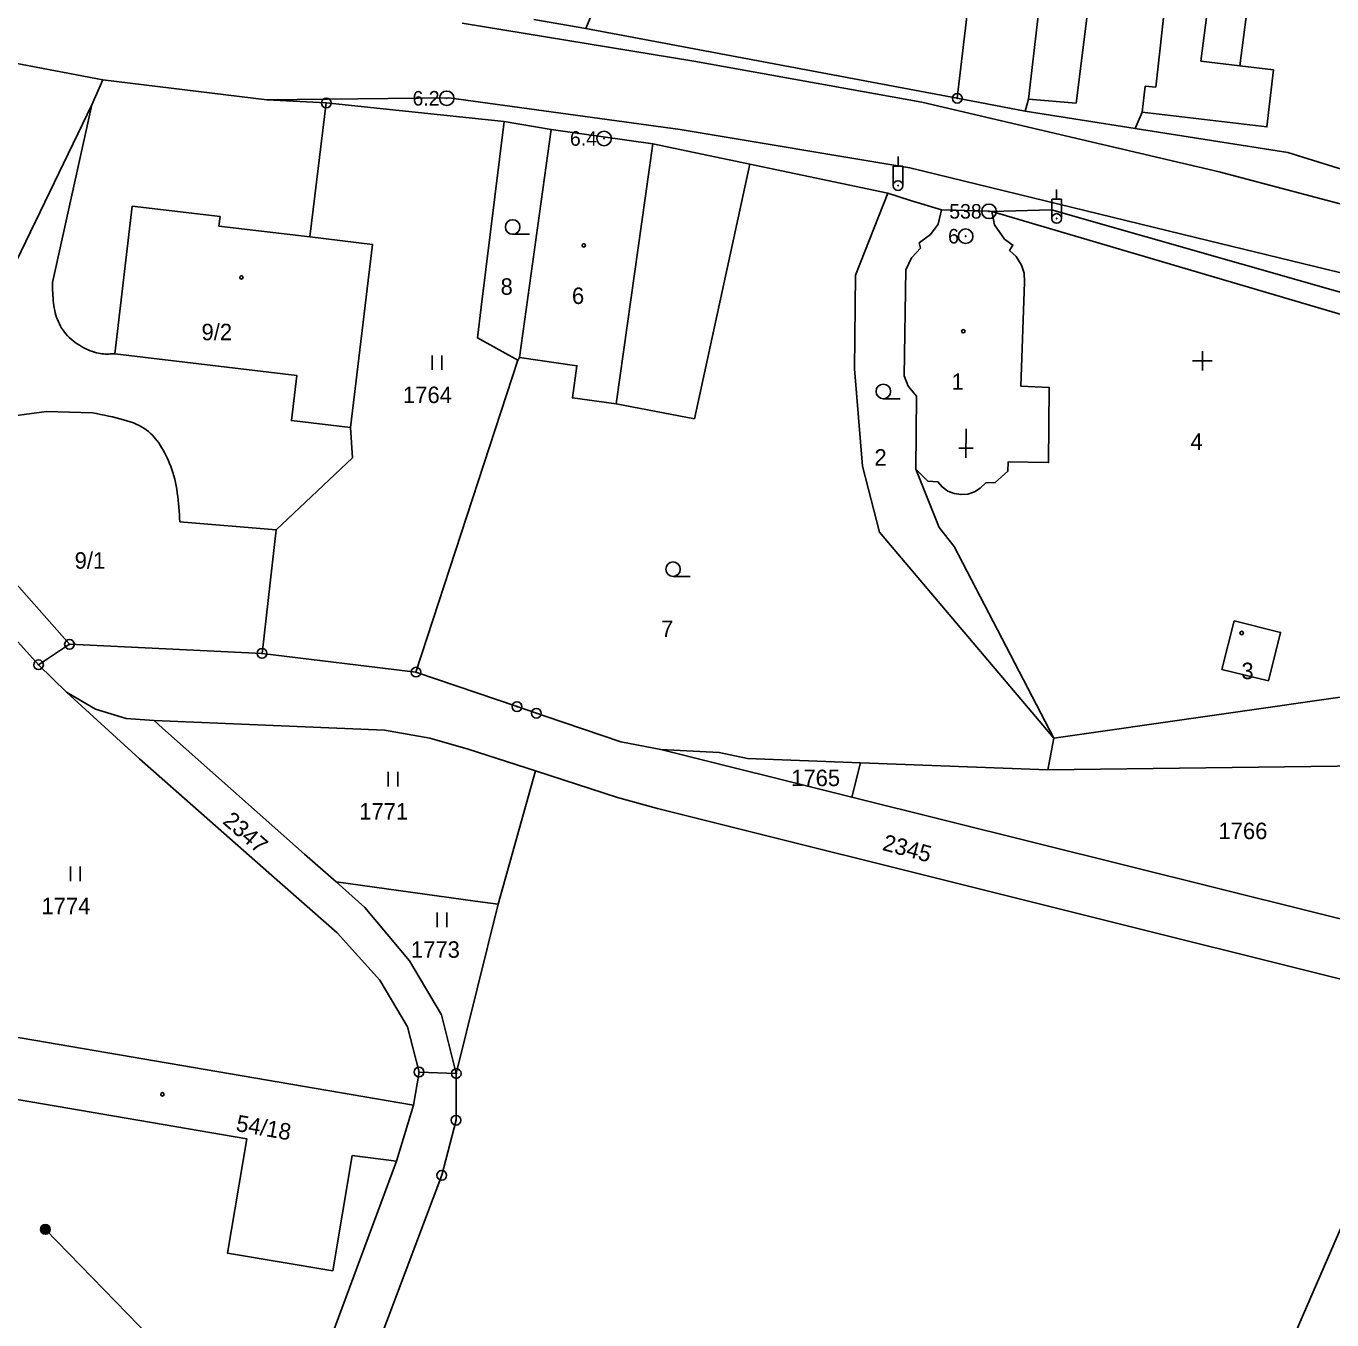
# Model space of a CAD drawing. Extents: x -504988 to -494607, y -1123820 to -1114018.
# Drawn here: x -501208.2 to -501073.4, y -1121149.7 to -1121016.1 of the extents above; entities that cross this region are included whole.
import ezdxf

# ---------------------------------------------------------------- set-up
doc = ezdxf.new("R2010")
doc.units = 0
for name, color, linetype in [('Hranice parcel', 7, 'Continuous'), ('Parcelní čísla', 7, 'Continuous'), ('Poz předměty', 7, 'Continuous'), ('Vnitřní kresba', 7, 'Continuous'), ('Značky bodu BP', 7, 'Continuous'), ('Značky budov', 7, 'Continuous'), ('Značky kultur', 7, 'Continuous')]:
    doc.layers.add(name, color=color, linetype=linetype)

msp = doc.modelspace()

# ---------------------------------------------------------------- linework, layer by layer
at = {"layer": 'Hranice parcel'}
for p, q in [((-501150.45, -1121016.36), (-501142.32, -1120996.7)), ((-501112.09, -1121023.57), (-501109.46, -1121001.03)), ((-501155.79, -1121015.45), (-501150.45, -1121016.36)), ((-501112.09, -1121023.57), (-501150.45, -1121016.36)), ((-501200.31, -1121021.65), (-501210.08, -1121019.8)), ((-501105.09, -1121024.89), (-501112.09, -1121023.57)), ((-501178.95, -1121037.89), (-501177.24, -1121024.05)), ((-501105.09, -1121024.89), (-501093.7, -1121026.69)), ((-501154, -1121026.81), (-501158.86, -1121025.97)), ((-501154, -1121026.81), (-501157.3, -1121050.35)), ((-501119.24, -1121033.38), (-501133.49, -1121030.39)), ((-501157.45, -1121050.62), (-501167.98, -1121082.82)), ((-501157.3, -1121050.35), (-501157.45, -1121050.62)), ((-501206.95, -1121082.06), (-501203.75, -1121079.94)), ((-501203.75, -1121079.94), (-501183.87, -1121080.88)), ((-501183.87, -1121080.88), (-501167.98, -1121082.82)), ((-501204.07, -1121084.89), (-501206.95, -1121082.06)), ((-501102.12, -1121089.63), (-501102.75, -1121092.92)), ((-501142.71, -1121090.79), (-501122.96, -1121095.71)), ((-501122.96, -1121095.71), (-501122.08, -1121092.19)), ((-501122.08, -1121092.19), (-501102.75, -1121092.92)), ((-501159.48, -1121106.78), (-501155.65, -1121093.02)), ((-501159.48, -1121106.78), (-501163.82, -1121124.26)), ((-501168.24, -1121127.52), (-501213.95, -1121119.71)), ((-501167.66, -1121124.11), (-501168.24, -1121127.52)), ((-501163.82, -1121124.26), (-501167.66, -1121124.11)), ((-501168.24, -1121127.52), (-501169.98, -1121133.31))]:
    msp.add_line(p, q, dxfattribs=at)
for points in [[(-501101.8, -1120994.64), (-501102.21, -1121001.98), (-501104.74, -1121023.67), (-501105.09, -1121024.89)], [(-501093.7, -1121026.69), (-501092.98, -1121024.99), (-501080.12, -1121026.53), (-501079.42, -1121020.65), (-501082.9, -1121020.23), (-501081.16, -1121006.61), (-501081.39, -1121001.53), (-501085.46, -1120996.43)], [(-501200.31, -1121021.65), (-501201.45, -1121024.23), (-501217.51, -1121057.46), (-501215.31, -1121064.21), (-501211.36, -1121071.36), (-501203.75, -1121079.94)], [(-501177.24, -1121024.05), (-501183.37, -1121023.72), (-501200.31, -1121021.65)], [(-501177.24, -1121024.05), (-501169.71, -1121024.84), (-501161.17, -1121025.73), (-501158.86, -1121025.97)], [(-501158.86, -1121025.97), (-501161.25, -1121045.14), (-501161.64, -1121048.32), (-501157.45, -1121050.62)], [(-501093.7, -1121026.69), (-501077.94, -1121029.18), (-501062.45, -1121033.99)], [(-501133.49, -1121030.39), (-501143.52, -1121028.28), (-501154, -1121026.81)], [(-501157.3, -1121050.35), (-501151.36, -1121051.18), (-501151.83, -1121054.49), (-501147.29, -1121055.13), (-501139.23, -1121056.66), (-501133.49, -1121030.39)], [(-501119.24, -1121033.38), (-501122.58, -1121041.83), (-501122.71, -1121051.5), (-501121.86, -1121061.54), (-501120.11, -1121068.35), (-501102.12, -1121089.63)], [(-501113.71, -1121035.1), (-501116.9, -1121034.13), (-501119.24, -1121033.38)], [(-501174.73, -1121057.56), (-501180.84, -1121056.84), (-501180.29, -1121052.18), (-501199.08, -1121049.94), (-501197.27, -1121034.71), (-501188.2, -1121035.79), (-501188.32, -1121036.77), (-501178.95, -1121037.89)], [(-501113.71, -1121035.1), (-501114.05, -1121036.56), (-501114.85, -1121037.63), (-501116.01, -1121038.5), (-501115.89, -1121039.03), (-501116.31, -1121039.48), (-501116.8, -1121040.06), (-501117.38, -1121041.28), (-501117.56, -1121052.21), (-501117.14, -1121053.3), (-501116.29, -1121054.33), (-501116.36, -1121061.87)], [(-501116.36, -1121061.87), (-501115.13, -1121063.09), (-501114.09, -1121063.16), (-501113.66, -1121063.69), (-501113.07, -1121064.12), (-501112.39, -1121064.37), (-501111.69, -1121064.49), (-501110.99, -1121064.46), (-501110.32, -1121064.2), (-501109.71, -1121063.83), (-501109.13, -1121063.26), (-501108.16, -1121063.25), (-501106.85, -1121062.08), (-501106.84, -1121061.11), (-501102.65, -1121061.18), (-501102.59, -1121053.43), (-501105.51, -1121053.31), (-501105.14, -1121042.56), (-501105.17, -1121041.61), (-501105.47, -1121040.81), (-501106.02, -1121039.92), (-501106.68, -1121039.29), (-501106.34, -1121038.72), (-501107.2, -1121038.11), (-501108.23, -1121036.63), (-501108.5, -1121035.27)], [(-501108.5, -1121035.27), (-501108.81, -1121035.24), (-501113.71, -1121035.1)], [(-501063.26, -1121046.23), (-501102.35, -1121035.09), (-501108.5, -1121035.27)], [(-501102.12, -1121089.63), (-501053.56, -1121082.68), (-501054.38, -1121069.11), (-501058.95, -1121056.41), (-501068.58, -1121047.02), (-501108.5, -1121035.27)], [(-501174.73, -1121057.56), (-501172.48, -1121038.66), (-501178.95, -1121037.89)], [(-501221.94, -1121047.06), (-501221.21, -1121057.69), (-501219.34, -1121065.38), (-501214.91, -1121073.25), (-501206.95, -1121082.06)], [(-501183.87, -1121080.88), (-501182.42, -1121068.13), (-501174.53, -1121060.69), (-501174.73, -1121057.56)], [(-501102.12, -1121089.63), (-501112.39, -1121069.86), (-501113.97, -1121067.9), (-501116.36, -1121061.87)], [(-501083.51, -1121077.51), (-501084.76, -1121082.54), (-501079.95, -1121083.7), (-501078.7, -1121078.71), (-501083.51, -1121077.51)], [(-501167.98, -1121082.82), (-501157.54, -1121086.38), (-501155.54, -1121087.06), (-501154.65, -1121087.36), (-501146.81, -1121090.03), (-501142.71, -1121090.79)], [(-501167.66, -1121124.11), (-501168.85, -1121119.45), (-501171.71, -1121114.61), (-501176.11, -1121109.73), (-501183.16, -1121103.53), (-501196.52, -1121091.78), (-501204.07, -1121084.89)], [(-501204.07, -1121084.89), (-501201.08, -1121086.63), (-501197.89, -1121087.62), (-501195.01, -1121087.81)], [(-501155.65, -1121093.02), (-501162.58, -1121090.76), (-501166.56, -1121089.65), (-501171.22, -1121088.82), (-501195.01, -1121087.81)], [(-501195.01, -1121087.81), (-501194.14, -1121088.59), (-501179.48, -1121101.6), (-501176.23, -1121104.48)], [(-501142.71, -1121090.79), (-501136.66, -1121091.11), (-501133.74, -1121091.75), (-501122.08, -1121092.19)], [(-501102.75, -1121092.92), (-501056.56, -1121092.33), (-501051.9, -1121092.27)], [(-501061.26, -1121117.53), (-501066.14, -1121116.11), (-501143.04, -1121096.91), (-501147.16, -1121095.77), (-501155.65, -1121093.02)], [(-501122.96, -1121095.71), (-501066.17, -1121109.86), (-501058.24, -1121111.42)], [(-501176.23, -1121104.48), (-501161.88, -1121106.45), (-501159.48, -1121106.78)], [(-501176.23, -1121104.48), (-501173.27, -1121107.11), (-501168.63, -1121112.62), (-501165.33, -1121118.19), (-501163.82, -1121124.26)], [(-501149.92, -1121321.68), (-501129.41, -1121274.31), (-501114.18, -1121238.98), (-501089.44, -1121179.28), (-501072.39, -1121139.97), (-501061.26, -1121117.53)], [(-501213.95, -1121119.71), (-501215.01, -1121125.95), (-501185.45, -1121130.99), (-501187.44, -1121142.8), (-501176.56, -1121144.63), (-501174.56, -1121132.73), (-501169.98, -1121133.31)], [(-501149.92, -1121321.68), (-501163.66, -1121307.57), (-501169.62, -1121297.33), (-501176.8, -1121276.99), (-501180.86, -1121271.98), (-501185.74, -1121262.45), (-501194.99, -1121245.9), (-501198.92, -1121236.67), (-501199.55, -1121231.72), (-501199.14, -1121226.57), (-501197.4, -1121219.88), (-501165.31, -1121134.77), (-501163.84, -1121129.08), (-501163.82, -1121124.26)], [(-501169.98, -1121133.31), (-501204.19, -1121225.49), (-501204.3, -1121226.11), (-501204.08, -1121237.88)]]:
    msp.add_lwpolyline(points, dxfattribs=at)
at = {"layer": 'Poz předměty'}
for p, q in [((-501118.7, -1121030.58), (-501117.7, -1121030.58)), ((-501118.7, -1121032.58), (-501118.7, -1121030.58)), ((-501118.2, -1121030.58), (-501118.2, -1121029.58)), ((-501117.7, -1121032.58), (-501117.7, -1121030.58)), ((-501101.83, -1121033.98), (-501101.83, -1121032.98)), ((-501102.33, -1121033.98), (-501101.33, -1121033.98)), ((-501102.33, -1121035.98), (-501102.33, -1121033.98)), ((-501101.33, -1121035.98), (-501101.33, -1121033.98)), ((-501165.39, -1121182.36), (-501206.24, -1121140.35))]:
    msp.add_line(p, q, dxfattribs=at)
for centre, radius in [((-501118.2, -1121032.58), 0.5), ((-501118.2, -1121032.58), 0.0303), ((-501101.83, -1121035.98), 0.5), ((-501101.83, -1121035.98), 0.0303), ((-501206.24, -1121140.35), 0.5), ((-501206.24, -1121140.35), 0.4), ((-501206.24, -1121140.35), 0.3), ((-501206.24, -1121140.35), 0.2), ((-501206.24, -1121140.35), 0.1)]:
    msp.add_circle(centre, radius, dxfattribs=at)
at = {"layer": 'Vnitřní kresba'}
for p, q in [((-501085.19, -1121006.07), (-501086.95, -1121019.75)), ((-501097.99, -1121009.51), (-501099.82, -1121024.06)), ((-501091.59, -1121022.43), (-501090.24, -1121010.39)), ((-501163.19, -1121015.8), (-501139.29, -1121019.73)), ((-501139.29, -1121019.73), (-501115.74, -1121023.97)), ((-501086.95, -1121019.75), (-501082.9, -1121020.23)), ((-501092.98, -1121024.99), (-501092.68, -1121022.31)), ((-501092.68, -1121022.31), (-501091.59, -1121022.43)), ((-501164.6, -1121023.51), (-501183.37, -1121023.72)), ((-501140.69, -1121026.81), (-501164.6, -1121023.51)), ((-501115.74, -1121023.97), (-501085.06, -1121031.17)), ((-501099.82, -1121024.06), (-501104.74, -1121023.67)), ((-501201.45, -1121024.23), (-501205.51, -1121042.6)), ((-501116.98, -1121030.75), (-501140.69, -1121026.81)), ((-501143.52, -1121028.28), (-501147.29, -1121055.13)), ((-501086.2, -1121038.26), (-501116.98, -1121030.75)), ((-501085.06, -1121031.17), (-501063.44, -1121036.87)), ((-501063.35, -1121043.83), (-501086.2, -1121038.26)), ((-501217.51, -1121057.46), (-501206.12, -1121055.91)), ((-501206.12, -1121055.91), (-501201.38, -1121056.04)), ((-501192.35, -1121067.31), (-501182.42, -1121068.13))]:
    msp.add_line(p, q, dxfattribs=at)
for points in [[(-501205.51, -1121042.6), (-501205.5, -1121042.87), (-501205.5, -1121043.14), (-501205.49, -1121043.4), (-501205.48, -1121043.66), (-501205.47, -1121043.93), (-501205.45, -1121044.19), (-501205.42, -1121044.45), (-501205.4, -1121044.71), (-501205.36, -1121044.96), (-501205.32, -1121045.22), (-501205.28, -1121045.47), (-501205.22, -1121045.71), (-501205.16, -1121045.95), (-501205.08, -1121046.19), (-501205, -1121046.42), (-501204.9, -1121046.65), (-501204.8, -1121046.87), (-501204.68, -1121047.09), (-501204.56, -1121047.3), (-501204.42, -1121047.51), (-501204.28, -1121047.71), (-501204.12, -1121047.9), (-501203.95, -1121048.09), (-501203.77, -1121048.27), (-501203.58, -1121048.44), (-501203.38, -1121048.61), (-501203.17, -1121048.77), (-501202.95, -1121048.93), (-501202.73, -1121049.07), (-501202.5, -1121049.2), (-501202.28, -1121049.33), (-501202.05, -1121049.44), (-501201.82, -1121049.55), (-501201.6, -1121049.64), (-501201.38, -1121049.72), (-501201.17, -1121049.79), (-501200.97, -1121049.85), (-501200.77, -1121049.89), (-501200.58, -1121049.93), (-501200.4, -1121049.95), (-501200.22, -1121049.97), (-501200.05, -1121049.98), (-501199.88, -1121049.98), (-501199.72, -1121049.98), (-501199.56, -1121049.97), (-501199.4, -1121049.96), (-501199.24, -1121049.95), (-501199.08, -1121049.94)], [(-501201.38, -1121056.04), (-501200.96, -1121056.12), (-501200.54, -1121056.21), (-501200.13, -1121056.29), (-501199.72, -1121056.38), (-501199.32, -1121056.47), (-501198.93, -1121056.56), (-501198.54, -1121056.66), (-501198.17, -1121056.76), (-501197.82, -1121056.86), (-501197.48, -1121056.98), (-501197.15, -1121057.09), (-501196.85, -1121057.22), (-501196.57, -1121057.35), (-501196.3, -1121057.5), (-501196.06, -1121057.64), (-501195.83, -1121057.8), (-501195.61, -1121057.97), (-501195.41, -1121058.14), (-501195.22, -1121058.33), (-501195.04, -1121058.52), (-501194.87, -1121058.72), (-501194.7, -1121058.94), (-501194.54, -1121059.16), (-501194.39, -1121059.39), (-501194.24, -1121059.63), (-501194.09, -1121059.89), (-501193.94, -1121060.15), (-501193.8, -1121060.42), (-501193.67, -1121060.7), (-501193.53, -1121060.99), (-501193.41, -1121061.28), (-501193.29, -1121061.59), (-501193.18, -1121061.9), (-501193.07, -1121062.22), (-501192.98, -1121062.55), (-501192.89, -1121062.89), (-501192.81, -1121063.23), (-501192.74, -1121063.58), (-501192.68, -1121063.94), (-501192.63, -1121064.3), (-501192.58, -1121064.67), (-501192.54, -1121065.04), (-501192.5, -1121065.41), (-501192.46, -1121065.79), (-501192.43, -1121066.17), (-501192.4, -1121066.54), (-501192.38, -1121066.93), (-501192.35, -1121067.31)]]:
    msp.add_lwpolyline(points, dxfattribs=at)
at = {"layer": 'Značky bodu BP'}
for centre, radius in [((-501177.24, -1121024.05), 0.5), ((-501177.24, -1121024.05), 0.0303), ((-501164.8, -1121023.57), 0.75), ((-501164.8, -1121023.57), 0.03), ((-501112.09, -1121023.57), 0.5), ((-501112.09, -1121023.57), 0.0303), ((-501148.55, -1121027.72), 0.75), ((-501148.55, -1121027.72), 0.03), ((-501108.81, -1121035.24), 0.75), ((-501108.81, -1121035.24), 0.03), ((-501111.22, -1121037.81), 0.75), ((-501111.22, -1121037.81), 0.03), ((-501203.75, -1121079.94), 0.5), ((-501203.75, -1121079.94), 0.0303), ((-501183.87, -1121080.88), 0.5), ((-501206.95, -1121082.06), 0.5), ((-501183.87, -1121080.88), 0.0303), ((-501206.95, -1121082.06), 0.0303), ((-501167.98, -1121082.82), 0.5), ((-501167.98, -1121082.82), 0.0303), ((-501157.54, -1121086.38), 0.5), ((-501157.54, -1121086.38), 0.0303), ((-501155.54, -1121087.06), 0.5), ((-501155.54, -1121087.06), 0.0303), ((-501167.66, -1121124.11), 0.5), ((-501163.82, -1121124.26), 0.5), ((-501167.66, -1121124.11), 0.0303), ((-501163.82, -1121124.26), 0.0303), ((-501163.84, -1121129.08), 0.5), ((-501163.84, -1121129.08), 0.0303), ((-501165.31, -1121134.77), 0.5), ((-501165.31, -1121134.77), 0.0303)]:
    msp.add_circle(centre, radius, dxfattribs=at)
at = {"layer": 'Značky budov'}
for p, q in [((-501111.2, -1121060.7), (-501111.15, -1121057.7)), ((-501110.43, -1121059.71), (-501111.94, -1121059.69))]:
    msp.add_line(p, q, dxfattribs=at)
for centre in [(-501150.65, -1121038.76), (-501186, -1121042.07), (-501111.46, -1121047.62), (-501082.72, -1121078.78), (-501194.16, -1121126.41)]:
    msp.add_circle(centre, 0.175, dxfattribs=at)
at = {"layer": 'Značky kultur'}
for p, q in [((-501157.99, -1121037.61), (-501156.24, -1121037.61)), ((-501166.32, -1121051.62), (-501166.32, -1121050.12)), ((-501165.32, -1121051.62), (-501165.32, -1121050.12)), ((-501085.78, -1121050.69), (-501087.78, -1121050.69)), ((-501086.78, -1121051.69), (-501086.78, -1121049.69)), ((-501119.72, -1121054.59), (-501117.97, -1121054.59)), ((-501141.43, -1121072.94), (-501139.68, -1121072.94)), ((-501170.84, -1121094.62), (-501170.84, -1121093.12)), ((-501169.84, -1121094.62), (-501169.84, -1121093.12)), ((-501203.65, -1121104.39), (-501203.65, -1121102.89)), ((-501202.65, -1121104.39), (-501202.65, -1121102.89)), ((-501165.79, -1121109.15), (-501165.79, -1121107.65)), ((-501164.79, -1121109.15), (-501164.79, -1121107.65))]:
    msp.add_line(p, q, dxfattribs=at)
for centre in [(-501157.99, -1121036.86), (-501119.72, -1121053.84), (-501141.43, -1121072.19)]:
    msp.add_circle(centre, 0.75, dxfattribs=at)

# ---------------------------------------------------------------- texts
at = {"layer": 'Parcelní čísla'}
for s, p in [('8', (-501159.24, -1121043.86)), ('6', (-501151.87, -1121044.81)), ('9/2', (-501190.12, -1121048.55)), ('1', (-501112.68, -1121053.67)), ('1764', (-501169.32, -1121055.04)), ('4', (-501088.01, -1121059.87)), ('2', (-501120.64, -1121061.5)), ('9/1', (-501203.22, -1121072.14)), ('7', (-501142.67, -1121079.19)), ('3', (-501082.75, -1121083.54)), ('1765', (-501129.24, -1121094.59)), ('1771', (-501173.84, -1121098.04)), ('1766', (-501085.12, -1121100.06)), ('1774', (-501206.65, -1121107.81)), ('1773', (-501168.5, -1121112.31))]:
    msp.add_text(s, height=1.7, dxfattribs=at).set_placement(p)
for s, rotation, p in [('2347', 319, (-501188.03, -1121098.36)), ('2345', 345, (-501119.91, -1121101.17)), ('54/18', 350, (-501186.64, -1121130.18))]:
    msp.add_text(s, height=1.7, rotation=rotation, dxfattribs=at).set_placement(p)
at = {"layer": 'Značky bodu BP'}
for s, p in [('6.2', (-501168.33, -1121024.32)), ('6.4', (-501152.08, -1121028.47)), ('538', (-501112.91, -1121035.99)), ('6', (-501113.03, -1121038.56))]:
    msp.add_text(s, height=1.5, dxfattribs=at).set_placement(p)

doc.saveas('drawing.dxf')
